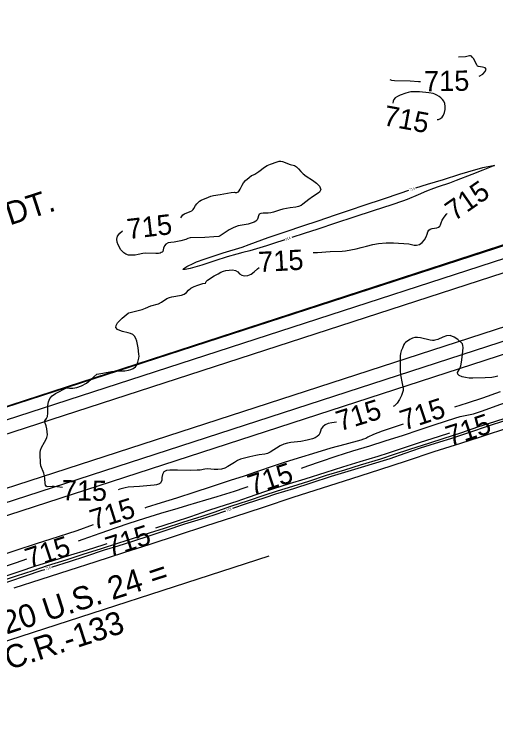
# Model space of a CAD drawing. Extents: x -468563856 to 36492962, y -306094093 to 11899197.
# Drawn here: x 1825166 to 1825949, y 531869 to 533036 of the extents above; entities that cross this region are included whole.
import ezdxf

# ---------------------------------------------------------------- set-up
doc = ezdxf.new("R2010")
doc.units = 0
for name, color, linetype in [('Default', 7, 'Continuous'), ('DT_X_Contour_Minor', 7, 'Continuous'), ('Level 14', 7, 'Continuous'), ('Level 19', 7, 'Continuous'), ('Level 40', 7, 'Continuous'), ('SC_Shading3', 7, 'Continuous')]:
    doc.layers.add(name, color=color, linetype=linetype)

msp = doc.modelspace()

# ---------------------------------------------------------------- linework, layer by layer
at = {"layer": 'Default'}
for points in [[(1824453.9, 532170), (1824460.1, 532150.9), (1827123.3, 533015.5), (1827116.5, 533036.4)], [(1824499.7, 532029.1), (1824505.9, 532010), (1827169, 532874.6), (1827162.8, 532893.7)]]:
    msp.add_lwpolyline(points, close=True, dxfattribs=at)
at = {"layer": 'DT_X_Contour_Minor'}
for points in [[(1825922.7, 532935.5), (1825928.3, 532939), (1825932.5, 532943.2), (1825934.1, 532947), (1825932.1, 532949.3), (1825928.1, 532950.5), (1825921.4, 532951.4), (1825919.9, 532952.2), (1825918.6, 532954), (1825913, 532964.4), (1825911.3, 532966.8), (1825909.9, 532968.2), (1825908.4, 532968.8), (1825906.7, 532968.7), (1825900.5, 532967.4), (1825888.8, 532966.6)], [(1825777, 532930.2), (1825780, 532929.2), (1825784.6, 532928.8), (1825810, 532927.9), (1825823.8, 532927.2), (1825827.1, 532927.2)], [(1825854.1, 532864.9), (1825856.5, 532865.3), (1825859.5, 532866.6), (1825862.2, 532868.8), (1825864.4, 532872.1), (1825866, 532876.3), (1825867, 532881.2), (1825867.1, 532886.4), (1825866.5, 532891), (1825865.1, 532894.7), (1825862.9, 532897.6), (1825860.2, 532900.1), (1825857.1, 532902.6), (1825853.8, 532904.8), (1825850.5, 532906.5), (1825847.5, 532907.5), (1825840.6, 532908.3), (1825825.4, 532910), (1825820.3, 532910.3), (1825815.5, 532910.2), (1825811.1, 532909.9), (1825807.1, 532909.1), (1825803.2, 532908), (1825794.1, 532904.6), (1825789.4, 532902.4), (1825785.6, 532900.1), (1825783.3, 532897.7), (1825782.3, 532895), (1825782.1, 532891.5)], [(1825437, 532705), (1825440.2, 532709.6), (1825443, 532711.4), (1825452.2, 532715), (1825454.6, 532716.4), (1825456.6, 532718.2), (1825458.1, 532720.3), (1825460.9, 532725.1), (1825462.7, 532727.7), (1825464.8, 532730.1), (1825467.1, 532732.2), (1825469.7, 532733.7), (1825481.7, 532738.7), (1825485.6, 532740), (1825490.1, 532741.1), (1825501, 532743.1), (1825518.6, 532746), (1825523.6, 532746.5), (1825525, 532746.4), (1825527.8, 532746.2), (1825529.2, 532746.6), (1825530.5, 532747.5), (1825531.9, 532749), (1825533.3, 532751.4), (1825536.5, 532758.2), (1825538.9, 532762), (1825542, 532765.5), (1825548.1, 532770.8), (1825551.9, 532773.7), (1825555, 532774.9), (1825557.3, 532776.1), (1825563.5, 532780.2), (1825573.1, 532787.5), (1825577.4, 532789.9), (1825582.9, 532792.2), (1825593.8, 532795.9), (1825597.1, 532797), (1825599.5, 532797.3), (1825602.1, 532796.7), (1825614.7, 532792), (1825622, 532790.1), (1825625.2, 532788.2), (1825628.6, 532784.8), (1825632.3, 532780.6), (1825636.2, 532776.4), (1825640.6, 532773), (1825651.2, 532766.1), (1825657.4, 532761.5), (1825662.4, 532756.3), (1825664.5, 532751.3), (1825662.4, 532746.9), (1825657.3, 532742.9), (1825650.9, 532738.9), (1825645, 532734.6), (1825635.6, 532727.1), (1825632.5, 532725), (1825628.3, 532723.2), (1825623.9, 532722.1), (1825615, 532721), (1825608.9, 532720.3), (1825602.7, 532719.2), (1825597.2, 532717.4), (1825587.9, 532713.9), (1825583.5, 532713.1), (1825579.2, 532712.7), (1825570.8, 532712.6), (1825567.2, 532712.1), (1825564.5, 532710.6), (1825563.2, 532707.9), (1825562.3, 532704.6), (1825561.2, 532701.6), (1825559.1, 532699.4), (1825556.2, 532697.9), (1825549.8, 532695.8), (1825546.3, 532694.8), (1825530, 532691.6), (1825522.9, 532689.1), (1825515.7, 532685.4), (1825509.1, 532681.1), (1825501, 532675.6), (1825498.8, 532674.7), (1825490.3, 532673.8), (1825475.6, 532672.9), (1825452.2, 532672.2), (1825448.4, 532671), (1825444.8, 532669.6), (1825437, 532667.5), (1825431.5, 532666.3), (1825425.7, 532665.4), (1825420.4, 532664.8), (1825415.9, 532663.9), (1825412.4, 532662.2), (1825410.1, 532659.1), (1825408.8, 532655.4)], [(1825819.5, 532753.5), (1825838.5, 532759.5), (1825864.2, 532767.3), (1825890.8, 532775.9), (1825904.2, 532779.7), (1825928.7, 532786.7), (1825945.1, 532790.3), (1825947.7, 532790.4), (1825944.9, 532788.9), (1825928.3, 532782.6), (1825910.6, 532775.7), (1825885.1, 532765.5), (1825874.3, 532761.5), (1825855.7, 532755.3), (1825847.9, 532752.8), (1825837, 532748.6), (1825822.9, 532742.6), (1825805, 532734.8), (1825797.6, 532732), (1825780.2, 532726.2), (1825749.7, 532716.4), (1825718.7, 532706.1), (1825688.7, 532696.2), (1825659.6, 532686.6), (1825637.8, 532679.5), (1825617.3, 532673.1)], [(1825606, 532669.2), (1825587.7, 532663), (1825576.5, 532659.4), (1825548.9, 532651.3), (1825537.5, 532648.2), (1825528, 532645.9), (1825512.2, 532641.2), (1825492.3, 532634.9), (1825470.9, 532627.9), (1825451.9, 532622.5), (1825443.9, 532620.8), (1825439.9, 532620.6), (1825441.4, 532622.5), (1825446.5, 532625.7), (1825457.7, 532631.3), (1825462.3, 532633.1), (1825474.5, 532637.3), (1825505.7, 532647.7), (1825536.4, 532657.3), (1825548.2, 532661.3), (1825579.2, 532672.6), (1825608.2, 532682.5), (1825635.2, 532691.6), (1825660.3, 532700.1), (1825688.7, 532709.6), (1825713.1, 532717.9), (1825735, 532725.5), (1825766.8, 532736), (1825794.1, 532745.3), (1825808, 532749.8)], [(1825652.1, 532648.2), (1825659.3, 532648.5), (1825679.7, 532650.1), (1825699.2, 532650.5), (1825704.7, 532651.3), (1825722.2, 532654.3), (1825730.4, 532656.5), (1825738.8, 532659), (1825749.3, 532661.3), (1825758.8, 532662.9), (1825771.1, 532664.2), (1825775, 532664.3), (1825782.8, 532663.9), (1825791.1, 532663.5), (1825799.8, 532663.2), (1825808.1, 532662.4), (1825816.4, 532660.6), (1825820.7, 532660.2), (1825825.1, 532661.4), (1825829.5, 532664.5), (1825833.5, 532669.1), (1825836.4, 532674.1), (1825838, 532678.5), (1825839, 532682.2), (1825840.4, 532685), (1825842.8, 532686.7), (1825846.1, 532687.7), (1825853.3, 532688.8), (1825856.3, 532689.7), (1825858.5, 532691.2), (1825859.6, 532693.6), (1825860.4, 532697), (1825862.1, 532701.2), (1825865.3, 532706), (1825869.3, 532710.9), (1825870.2, 532711.9)], [(1825408.8, 532655.4), (1825407.2, 532650.1), (1825406.2, 532649), (1825405, 532648.3), (1825403.1, 532647.6), (1825400.4, 532647), (1825396.2, 532646.7), (1825378.8, 532647.5), (1825374.7, 532647), (1825367.5, 532645.1), (1825362.6, 532644.3), (1825357, 532643.9), (1825351.7, 532644.3), (1825347.3, 532645.7), (1825343.8, 532647.8), (1825341, 532650.4), (1825338.7, 532653.5), (1825336.7, 532656.9), (1825334.9, 532660.8), (1825333.1, 532665.2), (1825332.4, 532670), (1825333.6, 532675), (1825337.4, 532679.9), (1825341.9, 532683.6)], [(1825244.1, 532265.4), (1825230.4, 532267.4), (1825227.4, 532267.5), (1825219.3, 532266.9), (1825217.4, 532267.6), (1825216.4, 532269.5), (1825216.1, 532272.3), (1825215.6, 532280.1), (1825214.9, 532284.5), (1825213.7, 532288.9), (1825209, 532301.1), (1825208.2, 532305.9), (1825207.5, 532319.3), (1825207.5, 532322.6), (1825208.2, 532326.2), (1825210, 532330.5), (1825214.9, 532339.5), (1825217.1, 532343.4), (1825218.6, 532347.2), (1825219.5, 532351.4), (1825219.4, 532356.2), (1825218.6, 532361.3), (1825217.4, 532365.9), (1825215.3, 532372.3), (1825215.3, 532374.4), (1825218.3, 532378.2), (1825219.7, 532381.5), (1825220.1, 532386.5), (1825220.1, 532392.7), (1825220.3, 532399.1), (1825221.4, 532405.1), (1825223.7, 532410.4), (1825227.5, 532414.9), (1825232.7, 532418.7), (1825238.3, 532421.7), (1825246.5, 532425.8), (1825249.7, 532427.6), (1825250.8, 532427.8), (1825255.7, 532427.4), (1825260.8, 532427.4), (1825267.6, 532428.4), (1825275.3, 532431), (1825283.2, 532435.7), (1825290.3, 532441.3), (1825300.2, 532450), (1825309.6, 532451.9), (1825324.1, 532454.4), (1825337.2, 532455.4), (1825345.6, 532455.9), (1825351.5, 532456.9), (1825355.3, 532457.9), (1825359.3, 532459.6), (1825362.8, 532462.1), (1825365.2, 532465.7), (1825366.7, 532469.7), (1825368.3, 532476.5), (1825368.7, 532479.3), (1825368.6, 532482.8), (1825367.1, 532493.3), (1825365.1, 532504.2), (1825363.7, 532508.6), (1825361.6, 532512.1), (1825358.5, 532514.8), (1825354.8, 532516.6), (1825351.2, 532517.8), (1825341.9, 532519.7), (1825337.6, 532521.1), (1825333.6, 532523.2), (1825331.2, 532526.1), (1825331.5, 532529.7), (1825333.8, 532533.7), (1825337.3, 532537.6), (1825341.3, 532541.3), (1825350.9, 532549.5), (1825352.1, 532550), (1825374, 532555.5), (1825379.5, 532557.7), (1825388, 532561.5), (1825400.4, 532564.9), (1825405.1, 532567.4), (1825414.1, 532573.3), (1825418.1, 532575.2), (1825422.1, 532576.3), (1825437.6, 532579), (1825442.4, 532580.8), (1825446, 532583.5), (1825449.1, 532586.8), (1825453, 532590.1), (1825458.6, 532593.1), (1825464.6, 532595.4), (1825472.8, 532597.8), (1825476.7, 532598.4), (1825477.3, 532599.3), (1825477.3, 532600.2), (1825478, 532601.1), (1825480.4, 532603.1), (1825491.3, 532610.3), (1825497.3, 532613.8), (1825502, 532616.3)], [(1825502, 532616.3), (1825506, 532617.8), (1825510.2, 532618.9), (1825515.4, 532619.9), (1825520.8, 532620.2), (1825525.7, 532619.3), (1825529.4, 532617), (1825532.5, 532613.9), (1825536, 532611.4), (1825540.6, 532610.3), (1825545.9, 532610.9), (1825551.3, 532613.2), (1825556.4, 532617.1), (1825561.5, 532621.7), (1825564.2, 532624)], [(1825952.9, 532446.9), (1825948.3, 532445.8), (1825943.1, 532445), (1825932.3, 532444.3), (1825912.3, 532443.8), (1825906.4, 532443.9), (1825900.4, 532444.6), (1825894.7, 532446), (1825890.1, 532447.9), (1825887.5, 532450.2), (1825887.4, 532452.7), (1825891.1, 532459.4), (1825892.7, 532464), (1825893.8, 532469.6), (1825895.4, 532482.4), (1825896.3, 532493.7), (1825896.1, 532497.1), (1825895.1, 532499.6), (1825892.4, 532502.4), (1825887.8, 532506.5), (1825881.9, 532510.5), (1825875.4, 532513), (1825869.1, 532512.7), (1825863.4, 532510.7), (1825855.1, 532506.8), (1825850.4, 532505.5), (1825848.5, 532505.1), (1825846.3, 532505.1), (1825842.9, 532505.6), (1825826.7, 532509.6), (1825821.9, 532510.2), (1825817.8, 532510), (1825813.8, 532508.8), (1825809.6, 532506.6), (1825802.6, 532501.6), (1825800.8, 532500), (1825799.9, 532498.6), (1825797.4, 532492.6), (1825795.7, 532488.1), (1825794.3, 532483.7), (1825793.8, 532480.2), (1825793.8, 532461.8), (1825794, 532455.9), (1825794.6, 532449.1), (1825797.1, 532435), (1825798.5, 532426.7), (1825798.6, 532423.5), (1825797.7, 532420.5), (1825795.8, 532415.3), (1825792.9, 532408.9), (1825789.1, 532403), (1825784.8, 532398.7), (1825782.7, 532397.4)], [(1825633.3, 532297.1), (1825643.7, 532300.8), (1825664.2, 532307.9), (1825689.9, 532316.4), (1825716.9, 532325.1), (1825744.7, 532333.7), (1825769.7, 532341.4), (1825799.2, 532350.7), (1825824.7, 532359.3), (1825851.1, 532368.1), (1825882.9, 532378.6), (1825891.8, 532381), (1825913.5, 532385.8), (1825926.1, 532390), (1825957.5, 532401.1), (1825976.1, 532407.4), (1826006.6, 532417.4), (1826035.1, 532427.2), (1826061.4, 532436), (1826092, 532446.5), (1826119.9, 532456), (1826145.1, 532464.4), (1826147.4, 532465.1)], [(1825956.6, 532421.5), (1825927.8, 532411.4), (1825902.7, 532402.8), (1825882.1, 532396.5)], [(1825690.1, 532371.8), (1825682.7, 532371.1), (1825676.7, 532369.8), (1825671.8, 532367.6), (1825668, 532364.6), (1825665.5, 532361.1), (1825664, 532357.6), (1825663, 532354.1), (1825661.5, 532351), (1825658.8, 532348.6), (1825655.3, 532346.7), (1825651.3, 532345.1), (1825642.7, 532342.5), (1825632.4, 532340.5), (1825621.1, 532339.2), (1825615.6, 532338.8), (1825610.3, 532338.1), (1825604.6, 532336.4), (1825598.5, 532333.3), (1825582.1, 532323.1), (1825577.9, 532321.2), (1825573.7, 532320), (1825564.1, 532318.6), (1825559, 532317.8), (1825548.9, 532315.4), (1825534.1, 532311.5), (1825529.1, 532309.5), (1825523.9, 532306.5), (1825513.4, 532299.7), (1825508.2, 532297.1), (1825502.8, 532295.5), (1825497.2, 532294.8), (1825491.2, 532295), (1825480.2, 532296), (1825476.1, 532295.6), (1825468.4, 532294.1), (1825463.4, 532293.6), (1825453, 532293.5), (1825431.3, 532294.1), (1825418.8, 532293.9), (1825413.2, 532293.1), (1825409.2, 532290.9), (1825407, 532286.9), (1825406.1, 532282), (1825405.6, 532277.6), (1825404.9, 532274.6), (1825403.8, 532272.8), (1825402.3, 532271.8), (1825400.2, 532270.9), (1825397.3, 532270.2), (1825393.3, 532269.6), (1825369.3, 532267.4), (1825350.8, 532266.1), (1825346.2, 532265.1), (1825337.7, 532262.7), (1825334.5, 532262)], [(1825521.2, 532231.7), (1825543.8, 532239.4), (1825574, 532249.4), (1825591.5, 532255.1), (1825621, 532264.2), (1825648.9, 532273.2), (1825682.2, 532283.9), (1825709.3, 532292), (1825736.6, 532300.2), (1825766.8, 532309.5), (1825777.6, 532313), (1825802, 532321.5), (1825827.2, 532330), (1825858.6, 532339.8), (1825876.2, 532345.5), (1825908.8, 532356.5), (1825934.2, 532364.9), (1825967.5, 532376)], [(1825966.1, 532378.8), (1825947.7, 532372.7), (1825920, 532363.7), (1825893.7, 532354.8), (1825863.4, 532344.7), (1825841.8, 532337.9), (1825809.2, 532327.7)], [(1825798.6, 532368.8), (1825793.8, 532367.1), (1825764.7, 532357.2), (1825750.5, 532351.9), (1825741.2, 532347.4), (1825737.8, 532345.7), (1825734.4, 532344.2), (1825729.9, 532342.8), (1825704, 532335.7), (1825681.1, 532329.6), (1825651.2, 532320.7), (1825633.3, 532315.2), (1825606.7, 532306.7), (1825590.2, 532301.3), (1825558.4, 532290.4), (1825539.8, 532284.3), (1825516.9, 532276.8), (1825484.8, 532266.2), (1825459.4, 532257.9), (1825429.9, 532248.4), (1825404.9, 532240.6), (1825380.4, 532232.8), (1825378.1, 532232)], [(1825396.2, 532199.8), (1825426.7, 532209.7), (1825453, 532218.3), (1825481, 532227.9), (1825499.4, 532234.2), (1825528.4, 532243.6), (1825547, 532249.8), (1825575, 532259.7), (1825586.8, 532263.7), (1825613.9, 532272.1), (1825639.4, 532280), (1825673.5, 532290.7), (1825700.5, 532299.3), (1825729, 532308), (1825758, 532316.8), (1825774.6, 532322), (1825794.4, 532328.6), (1825827.1, 532339.2), (1825856.1, 532348.5), (1825874.9, 532354.6)], [(1825809.2, 532327.7), (1825784.3, 532319.2), (1825762.1, 532311.9), (1825729, 532301.8), (1825703.1, 532294), (1825673.4, 532284.9), (1825644.4, 532275.5), (1825618.4, 532267.4), (1825593.5, 532259.6), (1825572.1, 532252.6), (1825546.4, 532244), (1825517.5, 532234.4), (1825490.6, 532225.1), (1825471, 532218.5), (1825439.7, 532208.6), (1825409.4, 532198.8), (1825385.4, 532191), (1825360.8, 532183), (1825333.9, 532174.4), (1825306.9, 532165.9), (1825277.3, 532156.2), (1825249.4, 532147.3), (1825219.3, 532137.8), (1825195.7, 532129.9), (1825168.8, 532121), (1825142.6, 532112.4)], [(1825270.1, 532178.6), (1825277.7, 532181.3), (1825305.7, 532191.2), (1825332.3, 532200.6), (1825352.4, 532207.5), (1825378.2, 532215.6), (1825404.3, 532223.6), (1825432.2, 532232.2), (1825448, 532236.9), (1825477.5, 532245.4), (1825495.8, 532250.9), (1825523.9, 532259.8), (1825541.5, 532265.8), (1825546.2, 532267.5)], [(1825226.9, 532136.1), (1825227.7, 532136.3), (1825255.7, 532145.3), (1825282.1, 532153.9), (1825312.4, 532163.9), (1825334.6, 532170.8), (1825358.8, 532178.3), (1825386.7, 532187.5), (1825412.7, 532196.2), (1825443.2, 532206.2), (1825470.2, 532214.7), (1825491, 532221.3), (1825509.8, 532227.8)], [(1825294.3, 532204.6), (1825267.4, 532195.2), (1825252.1, 532190.1), (1825225.1, 532181.4), (1825201.2, 532173.8), (1825168, 532163.2), (1825135.9, 532152.4), (1825117.5, 532146.1), (1825089.2, 532136.3), (1825064.5, 532127.7), (1825040.2, 532119.3), (1825009.5, 532108.7), (1824975.4, 532097.2), (1824965.9, 532094.3), (1824935.2, 532085.6), (1824907, 532077), (1824881.2, 532068.9), (1824857.3, 532061.4)], [(1824971.2, 532061.4), (1824988, 532066.8), (1825015.5, 532075.7), (1825049.8, 532086.9), (1825078, 532096.2), (1825102.3, 532104.2), (1825128.5, 532113.1), (1825155.7, 532122.9), (1825173.4, 532129), (1825200.8, 532137.9), (1825227.3, 532146.3), (1825257.6, 532155.7), (1825283.3, 532163.7), (1825312.1, 532172.7), (1825317.1, 532174.3)], [(1824675.7, 531982.2), (1824687.4, 531986), (1824713.8, 531994.8), (1824724.6, 531998), (1824746.6, 532004.3), (1824767.4, 532011), (1824794.4, 532020), (1824820.2, 532028.4), (1824845.8, 532036.7), (1824877.2, 532046.7), (1824902.6, 532054.5), (1824933.7, 532064.3), (1824966.4, 532074.7), (1824991.3, 532083), (1825022.8, 532093.6), (1825053.9, 532104.4), (1825075.6, 532111.9), (1825099.8, 532120.5), (1825122.2, 532127.8), (1825146.5, 532135.7), (1825169.4, 532143.7), (1825186, 532149.3)], [(1824715.4, 531969.2), (1824731.5, 531974), (1824747.1, 531978.9), (1824769, 531986.5), (1824791.5, 531994.4), (1824818.2, 532003.5), (1824843.9, 532011.5), (1824869, 532019.5), (1824896.9, 532028.5), (1824921.9, 532036.3), (1824951.7, 532045.5), (1824977, 532053.4), (1825002.3, 532061.5), (1825031.2, 532071.3), (1825056.4, 532080), (1825082.8, 532088.8), (1825102.7, 532095.1), (1825133.1, 532105), (1825158.2, 532113.2), (1825183.8, 532121.7), (1825210.8, 532130.8), (1825215.4, 532132.3)]]:
    msp.add_lwpolyline(points, dxfattribs=at)
at = {"layer": 'Level 14'}
msp.add_lwpolyline([(1825975.3, 532364.6), (1825922.3, 532347.3), (1825891.9, 532337.5), (1825848.8, 532323.5), (1825803.9, 532308.7), (1825760.4, 532294.5), (1825714.9, 532279.8), (1825666.9, 532264.4), (1825619.3, 532249.1), (1825570.6, 532233.1), (1825522.7, 532217.5), (1825477.2, 532202.5), (1825430.9, 532187.3), (1825386.1, 532172.9), (1825343.4, 532159.1), (1825298.4, 532144.6), (1825254.3, 532130.5), (1825208.8, 532115.9), (1825164.8, 532101.6)], dxfattribs=at)
at = {"layer": 'Level 40'}
msp.add_line((1824793.6, 531899), (1825580.4, 532154.4), dxfattribs=at)
at = {"layer": 'SC_Shading3'}
for points in [[(1824466.9, 532129.9), (1824453.9, 532170), (1827117.1, 533034.5), (1827130.1, 532994.5)], [(1824492.9, 532050), (1824505.8, 532010.1), (1827169, 532874.7), (1827156, 532914.7)]]:
    msp.add_lwpolyline(points, close=True, dxfattribs=at)

# ---------------------------------------------------------------- texts
at = {"layer": 'Level 19'}
for s, height, rotation, p in [('715', 33, 0.974, (1825833.1, 532910.8)), ('715', 33, 349.5214, (1825765, 532856)), ('714', 4, 17.5325, (1825809.4, 532748.2)), ('715', 33, 34.9676, (1825882.1, 532698.6)), ('715', 33, 6.7151, (1825350.9, 532670)), ('714', 4, 18.9076, (1825607.3, 532667.6)), ('715', 33, 3.2773, (1825563.8, 532616.4)), ('715', 33, 17.2117, (1825695.6, 532356.9)), ('715', 33, 18.2602, (1825800.2, 532358.2)), ('715', 33, 18.2716, (1825874.7, 532332.4)), ('715', 33, 18.1914, (1825552.3, 532252.7)), ('715', 33, 359.0956, (1825242.8, 532244.8)), ('715', 33, 17.4638, (1825294.9, 532196.2)), ('718', 4, 19.1139, (1825511.2, 532226.2)), ('715', 33, 17.8419, (1825320.6, 532151.8)), ('715', 33, 18.1513, (1825189.9, 532133.3)), ('718', 4, 18.1055, (1825216.8, 532130.7))]:
    msp.add_text(s, height=height, rotation=rotation, dxfattribs=at).set_placement(p)
at = {"layer": 'Level 40'}
for s, p in [('HELLEMIN ST. DT.', (1824819.1, 532582.2)), ('STA. 1580+82.20 U.S. 24 =', (1824833.2, 531922.2)), ('STA. 7+49.82 C.R.-133', (1824850.5, 531868.7))]:
    msp.add_text(s, height=37.5, rotation=17.9864, dxfattribs=at).set_placement(p)

doc.saveas('drawing.dxf')
